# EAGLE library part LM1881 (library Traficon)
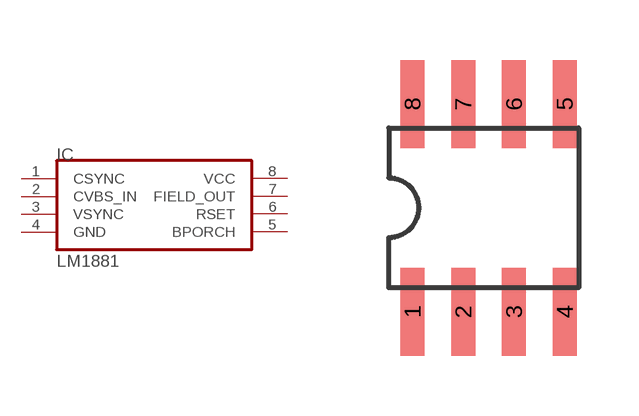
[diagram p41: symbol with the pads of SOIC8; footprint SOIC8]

Designator prefix IC

## LM1881M  [SOIC8]
1  CSYNC  out
2  CVBS_IN  in
3  VSYNC  out
4  GND  pas
5  BPORCH  out
6  RSET  pas
7  FIELD_OUT  out
8  VCC  pas

## Footprint SOIC8 (pad centres in mm)
Small Outline IC
smd 0.6 x 2.2: 1 -1.905,-2.6; 2 -0.635,-2.6; 3 0.635,-2.6; 4 1.905,-2.6; 5 1.905,2.6; 6 0.635,2.6; 7 -0.635,2.6; 8 -1.905,2.6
